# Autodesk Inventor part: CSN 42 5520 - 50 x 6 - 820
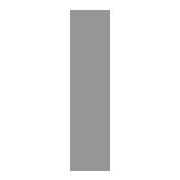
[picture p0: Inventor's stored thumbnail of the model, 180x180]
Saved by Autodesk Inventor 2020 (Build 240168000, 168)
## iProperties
Created: 2019-01
Part Number: CSN 42 5520 - 50 x 6 - 820
Material: Ocel
Description: Tyč
Document SubType Name: Modeling
Standard: CSN 42 5520
Designer: doma
Standards Organization: CSN
Language: cs-CZ
Size Designation: 50 x 6 - 820
Categories: <MemberInstance><Categories><Category DisplayName="Konstrukční profily" InternalName="089c4875-fa83-4c05-b084-43b9cc11f5ed" Mnemonic="GRDR"><CategoryParameter D
Stock Number: 50 x 6
Density: 7.85 g/cm^3
Appearance: Plech
Mass: 1931.1 g
Surface Area: 924.4 cm^2
Volume: 246 cm^3
IsCustomPart: 1
G_L: 820,000 mm
Author: doma
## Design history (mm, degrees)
node "Počáteční rovina"
node "Koncová rovina"
sketch "Náčrt"
  geometry: L1 (3, -25)-(-3, -25); L2 (-3, -25)-(-3, 25); L3 (-3, 25)-(3, 25); L4 (3, 25)-(3, -25); L5 (-6, 0)-(8, 0); L6 (0, -30)-(0, 40); L7 (0, 54)-(0, -44) reference; L8 (-9.2, 0)-(13.2, 0) reference
  constraints: 12 end point, 2 collinear, 2 parallel, 1 horizontal, 1 perpendicular
  dimensions: "d0" = 50 distance between parallel lines of L3 L1 (= G_W); "d1" = 6 distance between parallel lines of L4 L2 (= G_H); "d4" = 3 distance between parallel lines of L6 L4 (= 0.5 x d1); "d5" = 25 distance between parallel lines of L5 L3 (= 0.5 x d0)
extrude "Těleso" new body sketch "Náčrt" stored distance "d2" = 820 (= G_L); taper "d3" = 0 deg
node "Driven Length"
  sketch "Sketch3"
    geometry: L1 (0, 0)-(10, 0) reference
    constraints: 2 end point, 1 horizontal
  workplane "Work Plane3"
  sketch "Sketch4"
    geometry: L1 (-2, 0)-(12, 0) reference; L2 (-2, 820)-(12, 820) reference
    dimensions: "d9" = 820 distance between parallel lines of L1 L2 (derived)
body "Solid1"
other parameters: "G_W" = 50 [user parameter; used in 1 equation term], "G_H" = 6 [user parameter; used in 1 equation term], "G_L" = 820 (= d9) [user parameter; used in 1 equation term], "G_OFFSET_START" = 0 [user parameter; used in 1 equation term], "G_OFFSET_END" = 0 [user parameter; used in 1 equation term], "d6" = 0 (computed from G_OFFSET_START), "d8" = 90 deg
